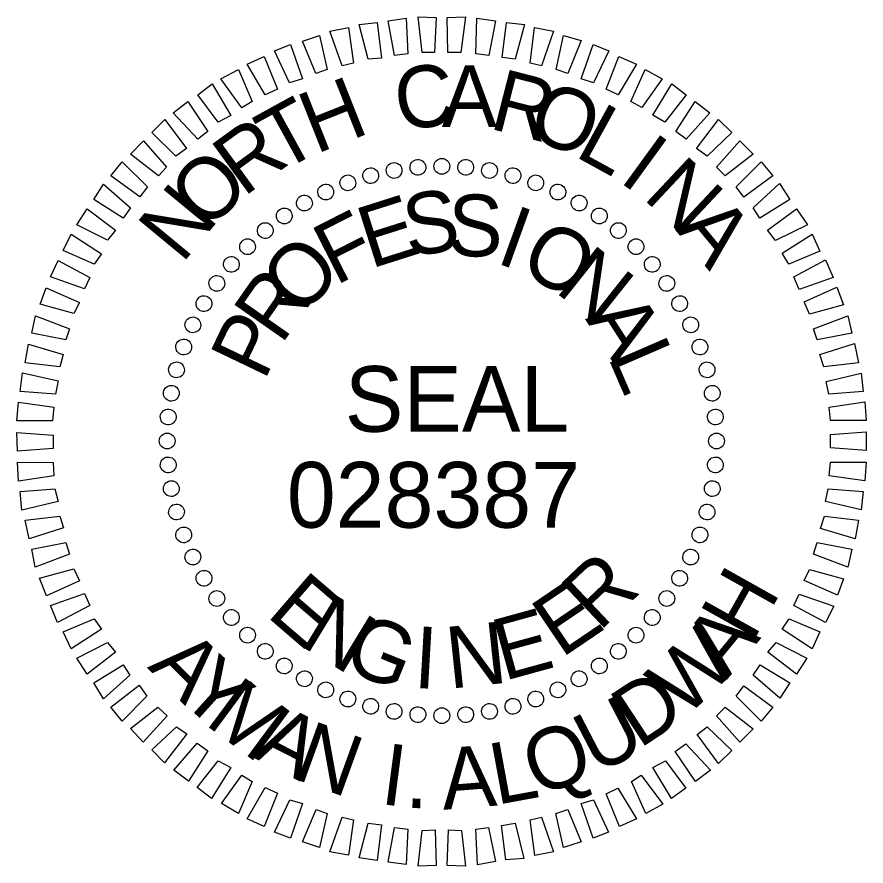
# Model space of a CAD drawing. Extents: x 1721764 to 1725755, y 971408 to 972569.
# Drawn here: x 1723744.1 to 1723831.2, y 972348 to 972435.1 of the extents above; entities that cross this region are included whole.
import ezdxf

# ---------------------------------------------------------------- set-up
doc = ezdxf.new("R2010")
doc.units = 0
doc.layers.add('Matchline Text', color=7, linetype='Continuous')

msp = doc.modelspace()

# ---------------------------------------------------------------- linework, layer by layer
at = {"layer": 'Matchline Text'}
for p, q in [((1723782.776, 972419.321), (1723782.776, 972419.321)), ((1723785.194, 972419.659), (1723785.194, 972419.659)), ((1723787.668, 972419.828), (1723787.668, 972419.828)), ((1723790.143, 972419.659), (1723790.143, 972419.659)), ((1723792.561, 972419.321), (1723792.561, 972419.321)), ((1723780.357, 972418.815), (1723780.357, 972418.815)), ((1723794.979, 972418.815), (1723794.979, 972418.815)), ((1723777.995, 972418.084), (1723777.995, 972418.084)), ((1723797.341, 972418.084), (1723797.341, 972418.084)), ((1723775.802, 972417.128), (1723775.802, 972417.128)), ((1723799.591, 972417.128), (1723799.591, 972417.128)), ((1723773.609, 972416.003), (1723773.609, 972416.003)), ((1723801.784, 972416.003), (1723801.784, 972416.003)), ((1723771.528, 972414.654), (1723771.528, 972414.654)), ((1723803.808, 972414.71), (1723803.808, 972414.71)), ((1723769.503, 972413.248), (1723769.503, 972413.248)), ((1723805.833, 972413.192), (1723805.833, 972413.192)), ((1723767.704, 972411.504), (1723767.704, 972411.504)), ((1723807.576, 972411.561), (1723807.576, 972411.561)), ((1723766.017, 972409.761), (1723766.017, 972409.761)), ((1723809.32, 972409.705), (1723809.32, 972409.705)), ((1723764.555, 972407.736), (1723764.555, 972407.736)), ((1723810.726, 972407.736), (1723810.726, 972407.736)), ((1723763.205, 972405.656), (1723763.205, 972405.656)), ((1723812.075, 972405.656), (1723812.075, 972405.656)), ((1723762.08, 972403.462), (1723762.08, 972403.462)), ((1723813.2, 972403.462), (1723813.2, 972403.462)), ((1723761.124, 972401.213), (1723761.124, 972401.213)), ((1723814.156, 972401.213), (1723814.156, 972401.213)), ((1723760.393, 972398.907), (1723760.393, 972398.907)), ((1723814.887, 972398.907), (1723814.887, 972398.907)), ((1723759.887, 972396.489), (1723759.887, 972396.489)), ((1723815.393, 972396.433), (1723815.393, 972396.433)), ((1723759.549, 972394.071), (1723759.549, 972394.071)), ((1723815.731, 972394.015), (1723815.731, 972394.015)), ((1723759.437, 972391.596), (1723759.437, 972391.596)), ((1723815.899, 972391.54), (1723815.899, 972391.54)), ((1723759.606, 972389.122), (1723759.606, 972389.122)), ((1723815.787, 972389.066), (1723815.787, 972389.066)), ((1723759.943, 972386.704), (1723759.943, 972386.704)), ((1723815.45, 972386.704), (1723815.45, 972386.704)), ((1723760.449, 972384.285), (1723760.449, 972384.285)), ((1723814.887, 972384.229), (1723814.887, 972384.229)), ((1723761.18, 972381.923), (1723761.18, 972381.923)), ((1723814.156, 972381.923), (1723814.156, 972381.923)), ((1723762.136, 972379.674), (1723762.136, 972379.674)), ((1723813.256, 972379.674), (1723813.256, 972379.674)), ((1723763.261, 972377.481), (1723763.261, 972377.481)), ((1723812.132, 972377.481), (1723812.132, 972377.481)), ((1723764.611, 972375.4), (1723764.611, 972375.4)), ((1723810.782, 972375.4), (1723810.782, 972375.4)), ((1723766.017, 972373.432), (1723766.017, 972373.432)), ((1723809.263, 972373.432), (1723809.263, 972373.432)), ((1723767.704, 972371.632), (1723767.704, 972371.632)), ((1723807.633, 972371.632), (1723807.633, 972371.632)), ((1723769.503, 972369.945), (1723769.503, 972369.945)), ((1723805.777, 972369.945), (1723805.777, 972369.945)), ((1723771.472, 972368.483), (1723771.472, 972368.483)), ((1723803.808, 972368.539), (1723803.808, 972368.539)), ((1723773.553, 972367.133), (1723773.553, 972367.133)), ((1723801.784, 972367.133), (1723801.784, 972367.133)), ((1723775.746, 972366.008), (1723775.746, 972366.008)), ((1723799.534, 972366.008), (1723799.534, 972366.008)), ((1723777.995, 972365.052), (1723777.995, 972365.052)), ((1723780.357, 972364.321), (1723780.357, 972364.321)), ((1723794.979, 972364.321), (1723794.979, 972364.321)), ((1723797.285, 972365.052), (1723797.285, 972365.052)), ((1723782.776, 972363.815), (1723782.776, 972363.815)), ((1723785.194, 972363.477), (1723785.194, 972363.477)), ((1723790.086, 972363.534), (1723790.086, 972363.534)), ((1723792.561, 972363.815), (1723792.561, 972363.815)), ((1723787.612, 972363.365), (1723787.612, 972363.365))]:
    msp.add_line(p, q, dxfattribs=at)
for points in [[(1723782.832, 972431.188), (1723782.157, 972434.731), (1723784.013, 972435.012), (1723784.181, 972431.356)], [(1723785.644, 972431.469), (1723785.25, 972435.124), (1723787.106, 972435.068), (1723786.937, 972431.469)], [(1723788.287, 972431.469), (1723788.231, 972435.068), (1723790.086, 972435.124), (1723789.636, 972431.469)], [(1723791.155, 972431.356), (1723791.267, 972435.012), (1723793.179, 972434.731), (1723792.505, 972431.188)], [(1723777.433, 972430.119), (1723776.196, 972433.662), (1723778.108, 972434.056), (1723778.614, 972430.4)], [(1723780.132, 972430.794), (1723779.176, 972434.337), (1723781.032, 972434.562), (1723781.482, 972430.906)], [(1723793.854, 972430.963), (1723794.304, 972434.562), (1723796.16, 972434.337), (1723795.204, 972430.794)], [(1723796.722, 972430.4), (1723797.172, 972434.056), (1723799.141, 972433.662), (1723797.903, 972430.119)], [(1723774.734, 972429.332), (1723773.384, 972432.65), (1723775.127, 972433.212), (1723775.915, 972429.725)], [(1723799.422, 972429.725), (1723800.153, 972433.212), (1723801.953, 972432.706), (1723800.603, 972429.332)], [(1723772.034, 972428.376), (1723770.516, 972431.637), (1723772.147, 972432.312), (1723773.384, 972428.769)], [(1723801.953, 972428.769), (1723803.19, 972432.312), (1723804.821, 972431.637), (1723803.246, 972428.376)], [(1723769.56, 972427.138), (1723767.704, 972430.288), (1723769.447, 972431.075), (1723770.797, 972427.701)], [(1723804.539, 972427.701), (1723805.833, 972431.075), (1723807.633, 972430.288), (1723805.777, 972427.138)], [(1723767.141, 972425.789), (1723765.004, 972428.769), (1723766.804, 972429.725), (1723768.21, 972426.464)], [(1723807.07, 972426.464), (1723808.532, 972429.725), (1723810.276, 972428.769), (1723808.195, 972425.845)], [(1723764.723, 972424.327), (1723762.642, 972427.138), (1723764.105, 972428.263), (1723766.017, 972425.001)], [(1723809.32, 972425.058), (1723811.288, 972428.263), (1723812.75, 972427.138), (1723810.557, 972424.327)], [(1723762.642, 972422.583), (1723760.112, 972425.283), (1723761.63, 972426.464), (1723763.655, 972423.371)], [(1723811.682, 972423.371), (1723813.65, 972426.464), (1723815.168, 972425.283), (1723812.75, 972422.583)], [(1723760.393, 972420.84), (1723757.918, 972423.258), (1723759.268, 972424.608), (1723761.461, 972421.627)], [(1723813.819, 972421.627), (1723816.068, 972424.608), (1723817.418, 972423.258), (1723814.887, 972420.84)], [(1723758.593, 972418.815), (1723755.725, 972421.065), (1723757.075, 972422.415), (1723759.437, 972419.715)], [(1723815.843, 972419.715), (1723818.261, 972422.415), (1723819.611, 972421.065), (1723816.743, 972418.815)], [(1723756.681, 972416.678), (1723753.701, 972418.815), (1723754.882, 972420.277), (1723757.469, 972417.691)], [(1723817.868, 972417.691), (1723820.455, 972420.277), (1723821.636, 972418.815), (1723818.655, 972416.622)], [(1723754.994, 972414.485), (1723751.957, 972416.397), (1723752.97, 972417.972), (1723755.725, 972415.554)], [(1723819.611, 972415.554), (1723822.311, 972418.028), (1723823.379, 972416.397), (1723820.286, 972414.485)], [(1723753.363, 972412.236), (1723750.214, 972413.81), (1723751.282, 972415.441), (1723754.207, 972413.248)], [(1723821.073, 972413.248), (1723824.054, 972415.441), (1723825.179, 972413.81), (1723821.917, 972412.179)], [(1723752.014, 972409.761), (1723748.808, 972411.167), (1723749.652, 972412.854), (1723752.745, 972410.83)], [(1723822.592, 972410.886), (1723825.685, 972412.854), (1723826.472, 972411.111), (1723823.267, 972409.761)], [(1723751.001, 972407.23), (1723747.515, 972408.468), (1723748.302, 972410.155), (1723751.564, 972408.411)], [(1723823.773, 972408.468), (1723827.035, 972410.211), (1723827.822, 972408.411), (1723824.335, 972407.174)], [(1723749.933, 972404.7), (1723746.446, 972405.656), (1723747.065, 972407.343), (1723750.495, 972405.824)], [(1723824.841, 972405.881), (1723828.216, 972407.399), (1723828.89, 972405.599), (1723825.404, 972404.643)], [(1723749.089, 972402), (1723745.602, 972402.675), (1723745.996, 972404.475), (1723749.483, 972403.125)], [(1723825.797, 972403.125), (1723829.34, 972404.475), (1723829.734, 972402.675), (1723826.191, 972402)], [(1723748.471, 972399.245), (1723744.928, 972399.638), (1723745.265, 972401.55), (1723748.808, 972400.482)], [(1723826.472, 972400.482), (1723830.015, 972401.607), (1723830.409, 972399.638), (1723826.866, 972399.245)], [(1723748.021, 972396.433), (1723744.421, 972396.714), (1723744.646, 972398.626), (1723748.302, 972397.782)], [(1723827.091, 972397.726), (1723830.69, 972398.57), (1723830.915, 972396.714), (1723827.372, 972396.433)], [(1723827.428, 972395.083), (1723831.084, 972395.645), (1723831.196, 972393.733), (1723827.541, 972393.733)], [(1723747.739, 972393.677), (1723744.084, 972393.677), (1723744.253, 972395.589), (1723747.852, 972395.083)], [(1723747.796, 972390.865), (1723744.14, 972390.584), (1723744.084, 972392.496), (1723747.796, 972392.215)], [(1723827.541, 972392.271), (1723831.196, 972392.552), (1723831.196, 972390.64), (1723827.541, 972390.921)], [(1723747.852, 972388.053), (1723744.253, 972387.491), (1723744.14, 972389.459), (1723747.796, 972389.403)], [(1723827.541, 972389.459), (1723831.196, 972389.459), (1723831.084, 972387.547), (1723827.428, 972388.053)], [(1723748.302, 972385.41), (1723744.59, 972384.51), (1723744.421, 972386.422), (1723747.964, 972386.704)], [(1723827.316, 972386.704), (1723830.915, 972386.422), (1723830.69, 972384.567), (1723827.035, 972385.41)], [(1723748.864, 972382.711), (1723745.321, 972381.586), (1723744.928, 972383.498), (1723748.471, 972383.892)], [(1723826.922, 972383.892), (1723830.409, 972383.498), (1723830.071, 972381.586), (1723826.528, 972382.655)], [(1723749.483, 972380.011), (1723745.94, 972378.662), (1723745.602, 972380.517), (1723749.089, 972381.192)], [(1723826.191, 972381.192), (1723829.734, 972380.517), (1723829.34, 972378.662), (1723825.797, 972380.011)], [(1723750.495, 972377.256), (1723747.121, 972375.737), (1723746.39, 972377.537), (1723749.933, 972378.493)], [(1723825.404, 972378.437), (1723828.89, 972377.481), (1723828.272, 972375.794), (1723824.841, 972377.312)], [(1723751.564, 972374.725), (1723748.246, 972372.982), (1723747.515, 972374.725), (1723751.001, 972375.962)], [(1723824.335, 972375.906), (1723827.878, 972374.669), (1723827.035, 972372.982), (1723823.773, 972374.725)], [(1723752.745, 972372.307), (1723749.652, 972370.282), (1723748.808, 972372.026), (1723752.014, 972373.375)], [(1723823.323, 972373.375), (1723826.472, 972372.026), (1723825.685, 972370.282), (1723822.592, 972372.307)], [(1723754.207, 972369.945), (1723751.282, 972367.695), (1723750.214, 972369.326), (1723753.363, 972370.957)], [(1723821.973, 972370.957), (1723825.122, 972369.326), (1723824.054, 972367.695), (1723821.13, 972369.945)], [(1723755.669, 972367.583), (1723752.97, 972365.165), (1723751.957, 972366.795), (1723754.994, 972368.651)], [(1723820.342, 972368.651), (1723823.379, 972366.795), (1723822.367, 972365.221), (1723819.611, 972367.583)], [(1723757.412, 972365.446), (1723754.882, 972362.859), (1723753.701, 972364.321), (1723756.625, 972366.571)], [(1723818.655, 972366.514), (1723821.636, 972364.321), (1723820.455, 972362.859), (1723817.868, 972365.446)], [(1723759.493, 972363.421), (1723757.019, 972360.722), (1723755.725, 972362.128), (1723758.537, 972364.321)], [(1723816.743, 972364.321), (1723819.611, 972362.072), (1723818.261, 972360.722), (1723815.843, 972363.421)], [(1723761.518, 972361.565), (1723759.212, 972358.585), (1723757.918, 972359.935), (1723760.449, 972362.296)], [(1723814.887, 972362.296), (1723817.418, 972359.878), (1723816.068, 972358.529), (1723813.875, 972361.509)], [(1723763.655, 972359.822), (1723761.686, 972356.729), (1723760.168, 972357.854), (1723762.586, 972360.609)], [(1723812.694, 972360.553), (1723815.225, 972357.854), (1723813.706, 972356.673), (1723811.625, 972359.766)], [(1723766.017, 972358.135), (1723764.048, 972354.929), (1723762.586, 972356.054), (1723764.723, 972358.81)], [(1723810.613, 972358.81), (1723812.694, 972355.998), (1723811.232, 972354.929), (1723809.32, 972358.135)], [(1723768.21, 972356.673), (1723766.804, 972353.411), (1723765.061, 972354.423), (1723767.141, 972357.348)], [(1723808.139, 972357.348), (1723810.332, 972354.367), (1723808.589, 972353.411), (1723807.126, 972356.673)], [(1723770.797, 972355.492), (1723769.447, 972352.061), (1723767.704, 972352.849), (1723769.56, 972356.054)], [(1723805.72, 972355.998), (1723807.633, 972352.849), (1723805.889, 972352.061), (1723804.539, 972355.435)], [(1723773.384, 972354.423), (1723772.147, 972350.88), (1723770.516, 972351.499), (1723772.09, 972354.817)], [(1723803.246, 972354.817), (1723804.764, 972351.499), (1723803.19, 972350.88), (1723801.953, 972354.423)], [(1723775.915, 972353.411), (1723775.127, 972349.924), (1723773.384, 972350.487), (1723774.79, 972353.805)], [(1723800.603, 972353.805), (1723801.953, 972350.487), (1723800.153, 972349.924), (1723799.366, 972353.411)], [(1723778.614, 972352.736), (1723778.108, 972349.137), (1723776.196, 972349.474), (1723777.433, 972353.017)], [(1723797.903, 972353.017), (1723799.141, 972349.474), (1723797.229, 972349.081), (1723796.722, 972352.736)], [(1723781.482, 972352.23), (1723781.032, 972348.575), (1723779.176, 972348.856), (1723780.132, 972352.399)], [(1723795.204, 972352.399), (1723796.104, 972348.799), (1723794.248, 972348.631), (1723793.798, 972352.174)], [(1723784.181, 972351.78), (1723784.013, 972348.181), (1723782.157, 972348.406), (1723782.832, 972351.949)], [(1723786.993, 972351.724), (1723787.106, 972348.068), (1723785.25, 972348.012), (1723785.644, 972351.668)], [(1723789.693, 972351.668), (1723790.086, 972348.012), (1723788.231, 972348.068), (1723788.343, 972351.724)], [(1723792.448, 972351.949), (1723793.179, 972348.462), (1723791.324, 972348.125), (1723791.155, 972351.78)]]:
    msp.add_lwpolyline(points, close=True, dxfattribs=at)
for centre, major_axis in [((1723782.778, 972419.377), (-0.14, 0.797)), ((1723785.215, 972419.698), (-0.071, 0.806)), ((1723787.672, 972419.806), (0, 0.809)), ((1723790.128, 972419.698), (0.071, 0.806)), ((1723792.565, 972419.377), (0.14, 0.797)), ((1723780.378, 972418.845), (-0.209, 0.781)), ((1723794.965, 972418.845), (0.209, 0.781)), ((1723778.033, 972418.106), (-0.277, 0.76)), ((1723797.31, 972418.106), (0.277, 0.76)), ((1723775.762, 972417.165), (-0.342, 0.733)), ((1723799.581, 972417.165), (0.342, 0.733)), ((1723773.581, 972416.03), (-0.405, 0.701)), ((1723801.762, 972416.03), (0.405, 0.701)), ((1723771.508, 972414.709), (-0.464, 0.663)), ((1723803.835, 972414.709), (0.464, 0.663)), ((1723769.557, 972413.213), (-0.52, 0.62)), ((1723805.786, 972413.213), (0.52, 0.62)), ((1723767.745, 972411.552), (-0.572, 0.572)), ((1723807.598, 972411.552), (0.572, 0.572)), ((1723766.084, 972409.739), (-0.62, 0.52)), ((1723809.259, 972409.739), (0.62, 0.52)), ((1723764.587, 972407.789), (-0.663, 0.464)), ((1723810.756, 972407.789), (0.663, 0.464)), ((1723763.266, 972405.715), (-0.701, 0.405)), ((1723812.077, 972405.715), (0.701, 0.405)), ((1723762.131, 972403.535), (-0.733, 0.342)), ((1723813.212, 972403.535), (0.733, 0.342)), ((1723761.19, 972401.263), (-0.76, 0.277)), ((1723814.153, 972401.263), (0.76, 0.277)), ((1723760.451, 972398.919), (-0.781, 0.209)), ((1723814.892, 972398.919), (0.781, 0.209)), ((1723759.919, 972396.519), (-0.797, 0.14)), ((1723815.424, 972396.519), (0.797, 0.14)), ((1723759.598, 972394.081), (-0.806, 0.071)), ((1723815.745, 972394.081), (0.806, 0.071)), ((1723759.491, 972391.625), (-0.809, 0)), ((1723815.852, 972391.625), (0.809, 0)), ((1723759.598, 972389.169), (-0.806, -0.071)), ((1723815.745, 972389.169), (0.806, -0.071)), ((1723759.919, 972386.732), (-0.797, -0.14)), ((1723815.424, 972386.732), (0.797, -0.14)), ((1723760.451, 972384.331), (-0.781, -0.209)), ((1723814.892, 972384.331), (0.781, -0.209)), ((1723761.19, 972381.987), (-0.76, -0.277)), ((1723814.153, 972381.987), (0.76, -0.277)), ((1723762.131, 972379.715), (-0.733, -0.342)), ((1723813.212, 972379.715), (0.733, -0.342)), ((1723763.266, 972377.535), (-0.701, -0.405)), ((1723812.077, 972377.535), (0.701, -0.405)), ((1723764.587, 972375.461), (-0.663, -0.464)), ((1723810.756, 972375.461), (0.663, -0.464)), ((1723766.084, 972373.511), (-0.62, -0.52)), ((1723809.259, 972373.511), (0.62, -0.52)), ((1723767.745, 972371.698), (-0.572, -0.572)), ((1723807.598, 972371.698), (0.572, -0.572)), ((1723769.557, 972370.037), (-0.52, -0.62)), ((1723805.786, 972370.037), (0.52, -0.62)), ((1723771.508, 972368.541), (-0.464, -0.663)), ((1723803.835, 972368.541), (0.464, -0.663)), ((1723773.581, 972367.22), (-0.405, -0.701)), ((1723801.762, 972367.22), (0.405, -0.701)), ((1723775.762, 972366.085), (-0.342, -0.733)), ((1723799.581, 972366.085), (0.342, -0.733)), ((1723778.033, 972365.144), (-0.277, -0.76)), ((1723797.31, 972365.144), (0.277, -0.76)), ((1723780.378, 972364.405), (-0.209, -0.781)), ((1723794.965, 972364.405), (0.209, -0.781)), ((1723782.778, 972363.873), (-0.14, -0.797)), ((1723785.215, 972363.552), (-0.071, -0.806)), ((1723787.672, 972363.444), (0, -0.809)), ((1723790.128, 972363.552), (0.071, -0.806)), ((1723792.565, 972363.873), (0.14, -0.797))]:
    msp.add_ellipse(centre, major_axis=major_axis, ratio=0.999708, dxfattribs=at)

# ---------------------------------------------------------------- texts
for s, height, rotation, p in [('C', 6.335, 7.21987, (1723783.225, 972423.441)), ('A', 6.335, 0.02032, (1723787.668, 972423.835)), ('R', 6.335, 345.6211, (1723792.392, 972423.722)), ('H', 6.335, 21.61948, (1723774.734, 972421.023)), ('O', 6.335, 338.42116, (1723796.16, 972422.935)), ('T', 6.335, 28.81977, (1723771.078, 972419.111)), ('L', 6.335, 331.22088, (1723801.165, 972420.91)), ('R', 6.336, 36.02051, (1723767.31, 972416.58)), ('I', 6.334, 324.02014, (1723805.72, 972418.323)), ('O', 6.336, 43.22174, (1723763.486, 972413.037)), ('N', 6.336, 316.81891, (1723808.195, 972416.58)), ('N', 6.336, 50.4235, (1723761.012, 972409.719)), ('S', 6.335, 8.25561, (1723784.181, 972410.506)), ('E', 6.335, 17.61107, (1723780.357, 972409.269)), ('S', 6.335, 358.9004, (1723788.231, 972410.619)), ('I', 6.335, 340.1896, (1723793.067, 972409.944)), ('F', 6.335, 26.96703, (1723776.758, 972407.526)), ('A', 6.336, 309.61715, (1723811.569, 972413.318)), ('O', 6.336, 330.83348, (1723795.373, 972409.156)), ('O', 6.336, 45.68124, (1723773.103, 972404.208)), ('N', 6.336, 321.47661, (1723799.141, 972407.019)), ('R', 6.336, 55.03965, (1723771.191, 972401.396)), ('A', 6.336, 302.76027, (1723802.346, 972404.151)), ('P', 6.337, 64.39889, (1723769.447, 972397.684)), ('L', 6.337, 293.40085, (1723804.652, 972400.327)), ('R', 6.336, 43.48141, (1723803.808, 972371.983)), ('H', 6.299, 60.73165, (1723819.513, 972370.81)), ('E', 6.33, 319.27689, (1723769.56, 972373.727)), ('E', 6.336, 34.12409, (1723799.928, 972369.284)), ('N', 6.336, 328.63396, (1723772.934, 972370.746)), ('E', 6.33, 15.41176, (1723794.023, 972366.978)), ('G', 6.335, 337.99024, (1723777.264, 972368.328)), ('N', 6.335, 6.05639, (1723788.456, 972366.191)), ('W', 6.299, 43.41998, (1723812.556, 972363.046)), ('A', 6.299, 50.59751, (1723816.92, 972367.101)), ('I', 6.335, 356.7012, (1723784.688, 972366.303)), ('A', 6.299, 314.87741, (1723757.402, 972368.382)), ('Y', 6.299, 318.0362, (1723760.443, 972365.344)), ('M', 6.299, 323.44637, (1723763.228, 972362.629)), ('D', 6.299, 33.33639, (1723807.924, 972359.987)), ('U', 6.299, 27.49009, (1723803.498, 972357.341)), ('A', 6.299, 332.98191, (1723768.174, 972359.208)), ('N', 6.299, 340.08238, (1723772.231, 972357.072)), ('Q', 6.299, 19.99167, (1723797.434, 972355.068)), ('I', 6.299, 352.51894, (1723781.244, 972354.398)), ('A', 6.299, 4.4971, (1723787.821, 972353.774)), ('L', 6.299, 10.40958, (1723793.274, 972354.277)), ('.', 6.299, 357.74336, (1723783.879, 972353.999))]:
    msp.add_text(s, height=height, rotation=rotation, dxfattribs=at).set_placement(p)
for s, height, p in [('SEAL', 6.7397, (1723777.714, 972392.566)), ('028387', 6.7418, (1723771.771, 972382.725))]:
    msp.add_text(s, height=height, dxfattribs=at).set_placement(p)

doc.saveas('drawing.dxf')
